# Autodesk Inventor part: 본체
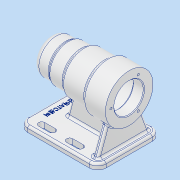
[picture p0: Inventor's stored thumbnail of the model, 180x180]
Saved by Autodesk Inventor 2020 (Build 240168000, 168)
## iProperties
Created: 2021-10
Part Number: 본체
Material: 알루미늄 6061
Document SubType Name: Modeling
Designer: user
Density: 2.7 g/cm^3
Appearance: 알루미늄 - 평지
Mass: 694.197 g
Surface Area: 698.877 cm^2
Volume: 257.11 cm^3
Author: user
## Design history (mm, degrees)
sketch "스케치1"
  geometry: L1 (-45, 56)-(45, 56); L2 (45, 56)-(45, -56); L3 (45, -56)-(-45, -56); L4 (-45, -56)-(-45, 56); L5 (-45, 56)-(45, -56); L6 (45, 56)-(-45, -56); 1 further point
  constraints: 12 end point, 2 midpoint, 2 parallel, 1 horizontal, 1 perpendicular
  dimensions: "d0" = 112 distance of L1.end L2.end; "d1" = 90 distance of L2.end L3.end
extrude "돌출1" new body sketch "스케치1" distance "d2" = 8; taper "d3" = 0 deg
fillet "모깎기1" dims "d4" = 12
fillet "모깎기2" dims "d5" = 3
sketch "스케치2"
  geometry: L1 (70, -56)-(70, 56); L2 (70, -56)-(95, -56); L3 (95, -56)-(95, -32); L4 (95, -32)-(97, -32); L5 (97, -32)-(97, -10); L6 (97, -10)-(100, -10); L7 (100, -10)-(100, 24); L8 (100, 24)-(104, 24); L9 (104, 24)-(104, 56); L10 (104, 56)-(70, 56); L11 (5, -56)-(0, -56) reference; L12 (0, -44)-(0, 44) reference; 3 further points
  constraints: 20 end point, 7 perpendicular, 2 midpoint, 2 vertical, 1 horizontal, 1 horizontal alignment
  dimensions: "d7" = 24 distance between parallel lines of L4 L2; "d8" = 112 distance between parallel lines of L10 L2; "d9" = 46 distance between parallel lines of L6 L2; "d10" = 80 distance between parallel lines of L2 L8; "d12" = 54 diameter of L5 L1; "d13" = 60 diameter of L7 L1; "d14" = 68 diameter of L9 L1; "d15" = 50 diameter of L3 L1; "d16" = 70 distance between parallel lines of L12 L1
revolve "회전1" sketch "스케치2" stored, may be unused: angle "d17" = 90 deg
sketch "스케치3"
  geometry: C1 r 34 at (0, 0) reference; 2 further points
  constraints: 1 coincident
hole "구멍1" sketch "스케치3" at (0, 0) diameter "d18" = 42; stored, may be unused: countersink angle "d22" = 90 deg, drill point angle "d24" = 0 deg; dims "d19" = 6, "d20" = 42, "d21" = 15, "d23" = 15
sketch "스케치4"
  geometry: C1 r 21 at (0, 0) reference; 2 further points
  constraints: 1 coincident
hole "구멍2" sketch "스케치4" at (0, 0) diameter "d25" = 48; stored, may be unused: countersink angle "d29" = 90 deg, drill point angle "d31" = 0 deg; dims "d26" = 6, "d27" = 48, "d28" = 54, "d30" = 54
sketch "스케치5"
  geometry: C1 r 24 at (0, 0) reference; 2 further points
  constraints: 1 coincident
hole "구멍3" sketch "스케치5" at (0, 0) diameter "d32" = 42; stored, may be unused: countersink angle "d36" = 90 deg, drill point angle "d38" = 0 deg; dims "d33" = 6, "d34" = 48, "d35" = 54, "d37" = 12
sketch "스케치6"
  geometry: C1 r 21 at (0, 0) reference; 2 further points
  constraints: 1 coincident
hole "구멍4" sketch "스케치6" at (0, 0) diameter "d39" = 35; stored, may be unused: countersink angle "d43" = 90 deg, drill point angle "d45" = 0 deg; dims "d40" = 6, "d41" = 48, "d42" = 54, "d44" = 18
sketch "스케치7"
  geometry: C1 r 17.5 at (0, 0) reference; 2 further points
  constraints: 1 coincident
hole "구멍5" sketch "스케치7" at (0, 0) diameter "d46" = 32; stored, may be unused: countersink angle "d50" = 90 deg, drill point angle "d52" = 0 deg; dims "d47" = 6, "d48" = 48, "d49" = 54, "d51" = 4
sketch "스케치8"
  geometry: C1 r 16 at (0, 0) reference; 2 further points
  constraints: 1 coincident
hole "구멍6" sketch "스케치8" at (0, 0) diameter "d53" = 21; stored, may be unused: countersink angle "d57" = 90 deg, drill point angle "d59" = 0 deg; dims "d54" = 6, "d55" = 48, "d56" = 54, "d58" = 3
fillet "모깎기3" dims "d60" = 3
fillet "모깎기4" dims "d61" = 0.3
chamfer "모따기1" distance "d62" = 1; stored, may be unused: second distance "d63" = 2, angle "d64" = 45 deg
fillet "모깎기5" dims "d65" = 3
fillet "모깎기6" dims "d66" = 8
sketch "스케치9"
  geometry: L1 (-33, 36)-(-33, 21); L2 (-37.5, 36)-(-37.5, 21); L3 (-28.5, 21)-(-28.5, 36); L4 (33, 56)-(-33, 56) reference; L5 (-33, -4)-(-33, -19); L6 (-37.5, -4)-(-37.5, -19); L7 (-28.5, -19)-(-28.5, -4); L8 (33, 56)-(-33, 56) reference; L9 (0, 56)-(0, -56); L10 (-33, -56)-(33, -56) reference; L11 (37.5, -4)-(37.5, -19); L12 (33, -4)-(33, -19); L13 (28.5, -19)-(28.5, -4); L14 (28.5, 21)-(28.5, 36); L15 (33, 36)-(33, 21); L16 (37.5, 36)-(37.5, 21); A1 r 4.5 centre (-33, 36) between (-28.5, 36) and (-37.5, 36); A2 r 4.5 centre (-33, 21) between (-37.5, 21) and (-28.5, 21); A3 r 4.5 centre (-33, -4) between (-28.5, -4) and (-37.5, -4); A4 r 4.5 centre (-33, -19) between (-37.5, -19) and (-28.5, -19); A5 r 4.5 centre (33, -4) between (37.5, -4) and (28.5, -4); A6 r 4.5 centre (33, -19) between (28.5, -19) and (37.5, -19); A7 r 4.5 centre (33, 21) between (28.5, 21) and (37.5, 21); A8 r 4.5 centre (33, 36) between (37.5, 36) and (28.5, 36); 5 further points
  constraints: 34 end point, 16 point on circle, 14 symmetric about line, 8 centre point, 8 tangent, 4 midpoint, 2 parallel, 2 vertical, 4 other
  dimensions: "d68" = 15 distance of L1.start L1.end; "d69" = 9 distance between parallel lines of L2 L3; "d70" = 20 distance from line of L4 L1.start; "d71" = 33 horizontal distance of point (0, 0) point (-33, 28.5); "d72" = 9 distance between parallel lines of L6 L7; "d73" = 15 distance of L5.start L5.end; "d74" = 25 distance of L5.start L1.end; "d75" = 33 horizontal distance of point (-33, -11.5) point (0, 0)
extrude "돌출2" cut sketch "스케치9" extent not by distance; stored distance "d76" = 0; taper "d77" = 0 deg
sketch "스케치10"
  geometry: L1 (-4, -48)-(4, -48); L2 (4, -48)-(4, 29); L3 (4, 29)-(-4, 29); L4 (-4, 29)-(-4, -48); L5 (-33, -56)-(33, -56) reference; 1 further point
  constraints: 8 end point, 2 parallel, 1 horizontal, 1 perpendicular
  dimensions: "d78" = 8 distance between parallel lines of L5 L1; "d79" = 8 distance of L2.end L3.end; "d80" = 77 distance of L1.end L2.end; "d81" = 4 distance from line of L2 point (0, 0)
extrude "돌출3" join sketch "스케치10" stored distance "d82" = 8; taper "d83" = 0 deg
sketch "스케치11"
  geometry: L1 (-38, 0)-(-29, 0) reference; L2 (-33.5, 0)-(-24.5, 0) reference; L3 (-29, 0)-(37, 0) reference; L4 (32.5, 0)-(41.5, 0) reference; L5 (37, 0)-(46, 0) reference; L6 (-33.5, 0)-(-24.5, 0) reference; L7 (-41, -3)-(-41, -8) reference; L8 (27.409, 37.342)-(41, 0); L9 (49, -8)-(49, -3) reference; L10 (-19.409, 37.342)-(-33, 0); A1 r 34 centre (4, 62) between (8, 28.236) and (0, 28.236) reference; A2 r 34 centre (4, 62) between (0, 28.236) and (8, 28.236) reference; A3 r 34 centre (4, 62) between (-19.409, 37.342) and (27.409, 37.342); 1 further point
  constraints: 4 end point, 4 point on circle, 2 point on line, 1 centre point, 1 coincident
  dimensions: "d92" = 110 deg angle of L10 L1; "d93" = 8 distance from line of L7 L10.end; "d94" = 110 deg angle of L8 L5; "d95" = 8 distance from line of L9 L8.end
extrude "돌출4" join sketch "스케치11" distance "d96" = 8; taper "d97" = 0 deg
feature "면 기울기1" dims angle "d98" = 15 deg
fillet "모깎기7" dims "d99" = 3
fillet "모깎기8" dims "d100" = 3
sketch "스케치12"
  geometry: C1 r 10.5 at (0, 0) reference; C2 r 26 at (0, 0); 3 further points
  constraints: 2 horizontal alignment, 1 centre point, 1 coincident, 1 other
  dimensions: "d101" = 52 diameter of C2
hole "구멍7" sketch "스케치12" at (-26, 0) diameter "d102" = 3.242; stored, may be unused: countersink angle "d106" = 82 deg, drill point angle "d108" = 118 deg; dims "d103" = 8, "d104" = 3.023, "d105" = 54, "d107" = 11
sketch "스케치13"
  geometry: L1 (33, 56)-(-33, 56) reference; 2 further points
  constraints: 1 vertical alignment, 1 other
  dimensions: "d112" = 12 distance from line of L1 point (0, 44)
feature "엠보싱1" sketch "스케치13" dims "d0" = 112, "d1" = 90, "d7" = 24, "d8" = 112, "d9" = 46, "d10" = 80, "d12" = 54, "d13" = 60, "d14" = 68, "d15" = 50, "d16" = 70, "d113" = 0.5, "d114" = 0
node "솔리드1"
pattern_circular "원형 패턴1" dims angle "d110" = 360 deg
feature "A9D066F2-1C7D-4E18-AEED-F7BC21143FA4" dims "d18" = 42, "d19" = 6, "d20" = 42, "d21" = 15, "d22" = 90 deg, "d23" = 15, "d24" = 0
